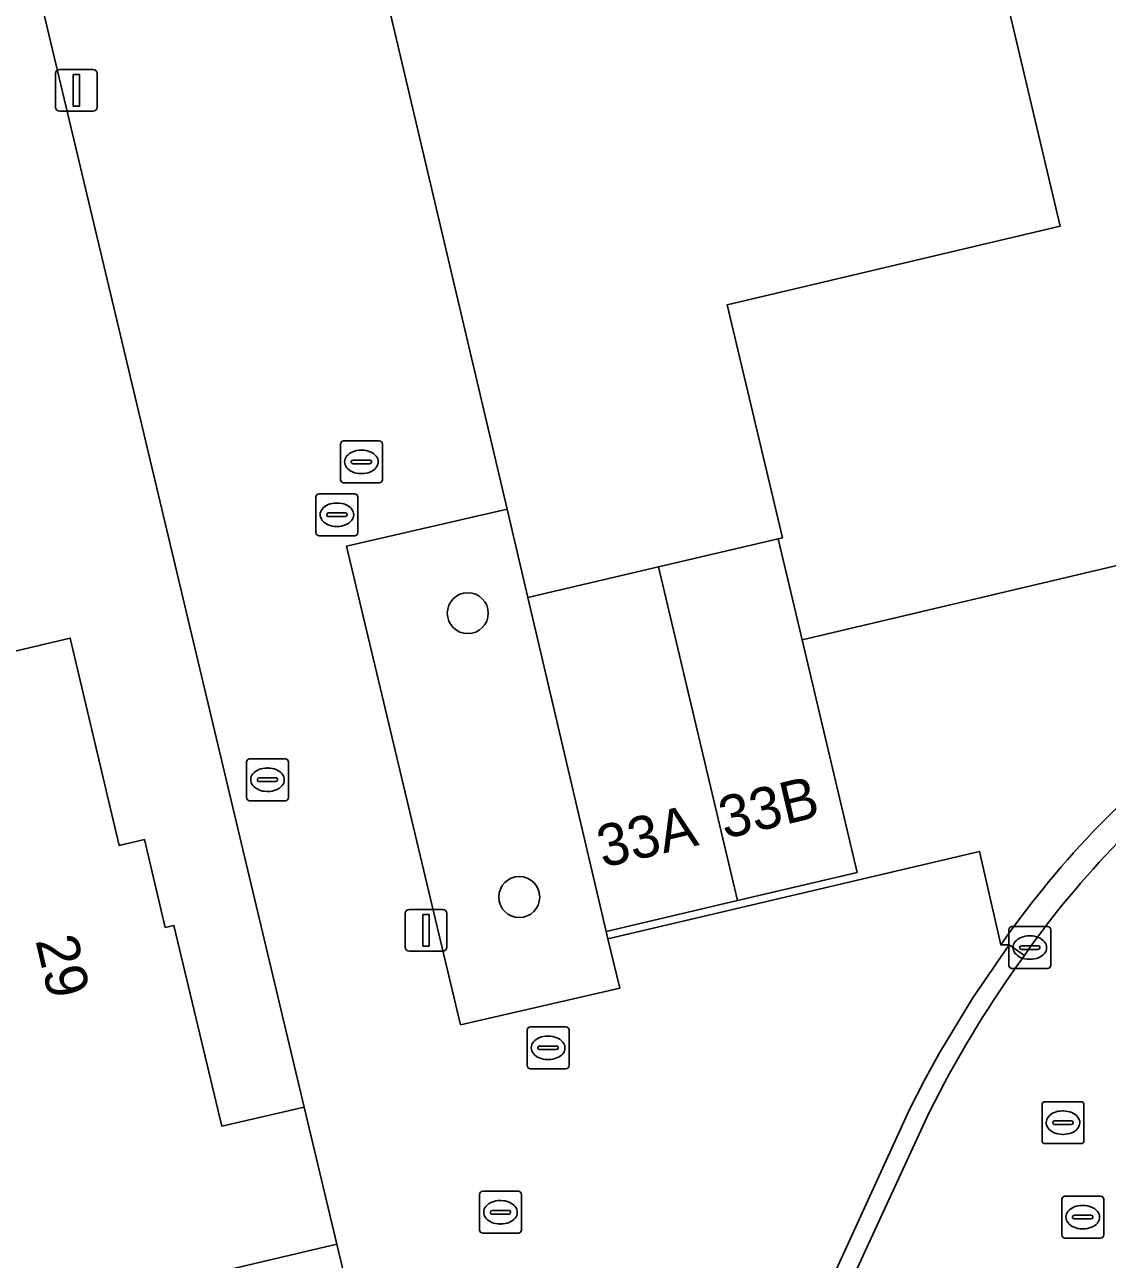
# Model space of a CAD drawing. Extents: x 157648 to 158502, y 379212 to 380938.
# Drawn here: x 158221.39 to 158247.23, y 380514.11 to 380543.57 of the extents above; entities that cross this region are included whole.
import ezdxf

# ---------------------------------------------------------------- set-up
doc = ezdxf.new("R2010")
doc.units = 0
for name, color, linetype in [('IMGEO_Boom', 7, 'Continuous'), ('IMGEO_Brandkraan', 7, 'Continuous'), ('IMGEO_Erf', 7, 'Continuous'), ('IMGEO_Groenvoorziening', 7, 'Continuous'), ('IMGEO_Hek', 7, 'Continuous'), ('IMGEO_Kolk', 7, 'Continuous'), ('IMGEO_Lichtmast', 7, 'Continuous'), ('IMGEO_Pand', 7, 'Continuous'), ('IMGEO_Pand_nummerreeks', 7, 'Continuous'), ('IMGEO_Rijbaan_lokaal_open', 7, 'Continuous'), ('IMGEO_Rioolput', 7, 'Continuous'), ('IMGEO_Voetpad_open', 7, 'Continuous')]:
    doc.layers.add(name, color=color, linetype=linetype)

msp = doc.modelspace()

# ---------------------------------------------------------------- linework, layer by layer
at = {"layer": 'IMGEO_Boom'}
for centre in [(158231.968, 380529.528), (158233.196, 380522.753)]:
    msp.add_circle(centre, 0.489, dxfattribs=at)
at = {"layer": 'IMGEO_Brandkraan'}
for p, q in [((158226.687, 380525.127), (158226.687, 380525.979)), ((158226.762, 380526.053), (158227.614, 380526.053)), ((158227.175, 380525.833), (158227.2, 380525.833)), ((158227.688, 380525.979), (158227.688, 380525.127)), ((158226.946, 380525.547), (158226.946, 380525.559)), ((158227.384, 380525.51), (158226.986, 380525.51)), ((158226.989, 380525.596), (158227.387, 380525.596)), ((158227.43, 380525.559), (158227.43, 380525.547)), ((158227.198, 380525.273), (158227.173, 380525.273)), ((158227.614, 380525.053), (158226.762, 380525.053))]:
    msp.add_line(p, q, dxfattribs=at)
for points in [[(158226.687, 380525.127), (158226.687, 380525.979)], [(158226.762, 380526.053), (158227.614, 380526.053)], [(158227.688, 380525.979), (158227.688, 380525.127)], [(158227.614, 380525.053), (158226.762, 380525.053)]]:
    msp.add_lwpolyline(points, dxfattribs=at)
for centre, radius, start, end in [((158226.764, 380525.977), 0.0765, 91.552, 178.448), ((158226.764, 380525.977), 0.0765, 91.552, 178.448), ((158227.612, 380525.977), 0.0765, 1.552, 88.448), ((158227.612, 380525.977), 0.0765, 1.552, 88.448), ((158226.986, 380525.556), 0.0403, 85.8775, 175.7526), ((158226.983, 380525.546), 0.0366, 178.938, 274.7102), ((158227.387, 380525.553), 0.043, 264.8664, 352.4533), ((158227.391, 380525.558), 0.0386, 1.7309, 96.639), ((158226.764, 380525.129), 0.0765, 181.552, 268.448), ((158226.764, 380525.129), 0.0765, 181.552, 268.448), ((158227.612, 380525.129), 0.0765, 271.552, 358.448), ((158227.612, 380525.129), 0.0765, 271.552, 358.448)]:
    msp.add_arc(centre, radius, start, end, dxfattribs=at)
for centre, major_axis, ratio, start_param, end_param in [((158227.174, 380525.553), (-0.387, 0.002), 0.722429, 4.712389, 7.853982), ((158227.199, 380525.553), (-0.39, 0.002), 0.717154, 1.570796, 4.712389)]:
    msp.add_ellipse(centre, major_axis=major_axis, ratio=ratio, start_param=start_param, end_param=end_param, dxfattribs=at)
at = {"layer": 'IMGEO_Erf'}
for points in [[(158207.911, 380501.03), (158215.154, 380502.738), (158222.749, 380504.529), (158220.849, 380512.586), (158218.887, 380512.123), (158216.994, 380520.152), (158208.234, 380518.086), (158206.561, 380525.179), (158222.48, 380528.933), (158223.648, 380523.983), (158224.253, 380524.126), (158224.748, 380522.028), (158224.955, 380522.077), (158226.095, 380517.285), (158228.061, 380517.741), (158218.496, 380557.919), (158216.938, 380564.64), (158206.036, 380574.234), (158181.237, 380547.104), (158161.46, 380525.323), (158161.459, 380525.322)], [(158226.289, 380559.958), (158230.238, 380543.354), (158232.907, 380532.013), (158233.403, 380529.904), (158236.519, 380530.635), (158239.376, 380531.305), (158239.475, 380531.328), (158238.162, 380536.889), (158246.107, 380538.764), (158244.27, 380546.547)], [(158248.401, 380530.889), (158239.946, 380528.893), (158241.258, 380523.342), (158238.401, 380522.667), (158235.273, 380521.928), (158235.314, 380521.754), (158244.18, 380523.842), (158244.692, 380521.61), (158244.875, 380521.874)]]:
    msp.add_lwpolyline(points, dxfattribs=at)
msp.add_arc((158263.238, 380508.736), 22.579, 126.1016, 144.417, dxfattribs=at)
at = {"layer": 'IMGEO_Groenvoorziening'}
msp.add_lwpolyline([(158235.314, 380521.754), (158235.273, 380521.928), (158233.403, 380529.904), (158232.907, 380532.013), (158229.076, 380531.128), (158231.797, 380519.705), (158235.594, 380520.58)], close=True, dxfattribs=at)
at = {"layer": 'IMGEO_Hek'}
for points in [[(158230.238, 380543.354), (158232.907, 380532.013)], [(158232.907, 380532.013), (158233.403, 380529.904)]]:
    msp.add_lwpolyline(points, dxfattribs=at)
at = {"layer": 'IMGEO_Kolk'}
for p, q in [((158228.344, 380531.451), (158228.344, 380532.303)), ((158228.419, 380532.377), (158229.271, 380532.377)), ((158229.345, 380532.303), (158229.345, 380531.451)), ((158228.832, 380532.157), (158228.857, 380532.157)), ((158228.603, 380531.871), (158228.603, 380531.883)), ((158229.041, 380531.834), (158228.643, 380531.834)), ((158228.646, 380531.92), (158229.044, 380531.92)), ((158229.087, 380531.883), (158229.087, 380531.871)), ((158229.271, 380531.377), (158228.419, 380531.377)), ((158228.855, 380531.597), (158228.83, 380531.597)), ((158244.88, 380521.121), (158244.88, 380521.973)), ((158244.955, 380522.047), (158245.807, 380522.047)), ((158245.881, 380521.973), (158245.881, 380521.121)), ((158245.368, 380521.827), (158245.393, 380521.827)), ((158245.139, 380521.541), (158245.139, 380521.553)), ((158245.577, 380521.504), (158245.179, 380521.504)), ((158245.182, 380521.59), (158245.58, 380521.59)), ((158245.623, 380521.553), (158245.623, 380521.541)), ((158245.391, 380521.267), (158245.366, 380521.267)), ((158245.807, 380521.047), (158244.955, 380521.047)), ((158232.248, 380514.804), (158232.248, 380515.656)), ((158232.323, 380515.73), (158233.175, 380515.73)), ((158232.736, 380515.51), (158232.761, 380515.51)), ((158233.249, 380515.656), (158233.249, 380514.804)), ((158232.507, 380515.224), (158232.507, 380515.236)), ((158232.945, 380515.187), (158232.547, 380515.187)), ((158232.55, 380515.273), (158232.948, 380515.273)), ((158232.991, 380515.236), (158232.991, 380515.224)), ((158232.759, 380514.95), (158232.734, 380514.95)), ((158233.175, 380514.73), (158232.323, 380514.73))]:
    msp.add_line(p, q, dxfattribs=at)
for points in [[(158228.344, 380531.451), (158228.344, 380532.303)], [(158228.419, 380532.377), (158229.271, 380532.377)], [(158229.345, 380532.303), (158229.345, 380531.451)], [(158229.271, 380531.377), (158228.419, 380531.377)], [(158244.88, 380521.121), (158244.88, 380521.973)], [(158244.955, 380522.047), (158245.807, 380522.047)], [(158245.881, 380521.973), (158245.881, 380521.121)], [(158245.807, 380521.047), (158244.955, 380521.047)], [(158232.248, 380514.804), (158232.248, 380515.656)], [(158232.323, 380515.73), (158233.175, 380515.73)], [(158233.249, 380515.656), (158233.249, 380514.804)], [(158233.175, 380514.73), (158232.323, 380514.73)]]:
    msp.add_lwpolyline(points, dxfattribs=at)
for centre, radius, start, end in [((158228.421, 380532.301), 0.0765, 91.552, 178.448), ((158228.421, 380532.301), 0.0765, 91.552, 178.448), ((158229.269, 380532.301), 0.0765, 1.552, 88.448), ((158229.269, 380532.301), 0.0765, 1.552, 88.448), ((158228.643, 380531.88), 0.0403, 85.8775, 175.7526), ((158228.64, 380531.87), 0.0366, 178.938, 274.7102), ((158229.044, 380531.877), 0.043, 264.8664, 352.4533), ((158229.048, 380531.882), 0.0386, 1.7309, 96.639), ((158228.421, 380531.453), 0.0765, 181.552, 268.448), ((158228.421, 380531.453), 0.0765, 181.552, 268.448), ((158229.269, 380531.453), 0.0765, 271.552, 358.448), ((158229.269, 380531.453), 0.0765, 271.552, 358.448), ((158244.957, 380521.971), 0.0765, 91.552, 178.448), ((158244.957, 380521.971), 0.0765, 91.552, 178.448), ((158245.805, 380521.971), 0.0765, 1.552, 88.448), ((158245.805, 380521.971), 0.0765, 1.552, 88.448), ((158245.179, 380521.55), 0.0403, 85.8775, 175.7526), ((158245.176, 380521.54), 0.0366, 178.938, 274.7102), ((158245.58, 380521.547), 0.043, 264.8664, 352.4533), ((158245.584, 380521.552), 0.0386, 1.7309, 96.639), ((158244.957, 380521.123), 0.0765, 181.552, 268.448), ((158244.957, 380521.123), 0.0765, 181.552, 268.448), ((158245.805, 380521.123), 0.0765, 271.552, 358.448), ((158245.805, 380521.123), 0.0765, 271.552, 358.448), ((158232.325, 380515.654), 0.0765, 91.552, 178.448), ((158232.325, 380515.654), 0.0765, 91.552, 178.448), ((158233.173, 380515.654), 0.0765, 1.552, 88.448), ((158233.173, 380515.654), 0.0765, 1.552, 88.448), ((158232.547, 380515.233), 0.0403, 85.8775, 175.7526), ((158232.544, 380515.223), 0.0366, 178.938, 274.7102), ((158232.948, 380515.23), 0.043, 264.8664, 352.4533), ((158232.952, 380515.235), 0.0386, 1.7309, 96.639), ((158232.325, 380514.806), 0.0765, 181.552, 268.448), ((158232.325, 380514.806), 0.0765, 181.552, 268.448), ((158233.173, 380514.806), 0.0765, 271.552, 358.448), ((158233.173, 380514.806), 0.0765, 271.552, 358.448)]:
    msp.add_arc(centre, radius, start, end, dxfattribs=at)
for centre, major_axis, ratio, start_param, end_param in [((158228.831, 380531.877), (-0.387, 0.002), 0.722429, 4.712389, 7.853982), ((158228.856, 380531.877), (-0.39, 0.002), 0.717154, 1.570796, 4.712389), ((158245.367, 380521.547), (-0.387, 0.002), 0.722429, 4.712389, 7.853982), ((158245.392, 380521.547), (-0.39, 0.002), 0.717154, 1.570796, 4.712389), ((158232.735, 380515.23), (-0.387, 0.002), 0.722429, 4.712389, 7.853982), ((158232.76, 380515.23), (-0.39, 0.002), 0.717154, 1.570796, 4.712389)]:
    msp.add_ellipse(centre, major_axis=major_axis, ratio=ratio, start_param=start_param, end_param=end_param, dxfattribs=at)
at = {"layer": 'IMGEO_Lichtmast'}
for p, q in [((158222.131, 380541.606), (158222.131, 380542.406)), ((158222.131, 380542.406), (158222.131, 380541.606)), ((158222.231, 380542.506), (158223.021, 380542.506)), ((158223.021, 380542.506), (158222.231, 380542.506)), ((158223.121, 380542.406), (158223.121, 380541.606)), ((158223.121, 380541.606), (158223.121, 380542.406)), ((158223.021, 380541.506), (158222.231, 380541.506)), ((158222.231, 380541.506), (158223.021, 380541.506)), ((158230.476, 380521.558), (158230.476, 380522.358)), ((158230.476, 380522.358), (158230.476, 380521.558)), ((158230.576, 380522.458), (158231.366, 380522.458)), ((158231.366, 380522.458), (158230.576, 380522.458)), ((158231.466, 380522.358), (158231.466, 380521.558)), ((158231.466, 380521.558), (158231.466, 380522.358)), ((158231.366, 380521.458), (158230.576, 380521.458)), ((158230.576, 380521.458), (158231.366, 380521.458))]:
    msp.add_line(p, q, dxfattribs=at)
for points in [[(158222.551, 380542.381), (158222.701, 380542.381), (158222.701, 380541.631), (158222.551, 380541.631), (158222.551, 380542.381)], [(158230.896, 380522.333), (158231.046, 380522.333), (158231.046, 380521.583), (158230.896, 380521.583), (158230.896, 380522.333)]]:
    msp.add_lwpolyline(points, dxfattribs=at)
for centre, start, end in [((158222.231, 380542.406), 90, 180), ((158222.231, 380542.406), 90, 180), ((158223.021, 380542.406), 0, 90), ((158223.021, 380542.406), 360, 90), ((158222.231, 380541.606), 180, 270), ((158222.231, 380541.606), 180, 270), ((158223.021, 380541.606), 270, 0), ((158223.021, 380541.606), 270, 0), ((158230.576, 380522.358), 90, 180), ((158230.576, 380522.358), 90, 180), ((158231.366, 380522.358), 0, 90), ((158231.366, 380522.358), 360, 90), ((158230.576, 380521.558), 180, 270), ((158230.576, 380521.558), 180, 270), ((158231.366, 380521.558), 270, 0), ((158231.366, 380521.558), 270, 0)]:
    msp.add_arc(centre, 0.1, start, end, dxfattribs=at)
at = {"layer": 'IMGEO_Pand'}
for points in [[(158254.07, 380537.657), (158252.147, 380545.356), (158252.047, 380545.332), (158251.36, 380548.241), (158247.079, 380547.23), (158244.27, 380546.547), (158246.107, 380538.764), (158238.162, 380536.889), (158239.475, 380531.328), (158239.376, 380531.305), (158239.946, 380528.893), (158248.401, 380530.889), (158248.359, 380531.07), (158250.471, 380531.569), (158250.256, 380532.48), (158255.026, 380533.607)], [(158239.946, 380528.893), (158239.376, 380531.305), (158236.519, 380530.635), (158238.401, 380522.667), (158241.258, 380523.342)], [(158236.519, 380530.635), (158233.403, 380529.904), (158235.273, 380521.928), (158238.401, 380522.667)], [(158220.849, 380512.586), (158228.842, 380514.468), (158228.061, 380517.741), (158226.095, 380517.285), (158224.955, 380522.077), (158224.748, 380522.028), (158224.253, 380524.126), (158223.648, 380523.983), (158222.48, 380528.933), (158206.561, 380525.179), (158208.234, 380518.086), (158216.994, 380520.152), (158218.887, 380512.123)], [(158216.91, 380495.301), (158231.694, 380498.797), (158231.45, 380500), (158230.488, 380504.077), (158231.09, 380504.219), (158230.682, 380505.946), (158230.849, 380505.985), (158229.701, 380510.871), (158228.842, 380514.468), (158220.849, 380512.586), (158222.749, 380504.529), (158215.154, 380502.738), (158215.8, 380500)]]:
    msp.add_lwpolyline(points, close=True, dxfattribs=at)
at = {"layer": 'IMGEO_Rijbaan_lokaal_open'}
for points in [[(158245.381, 380521.547), (158245.253, 380521.357)], [(158243.108, 380517.861), (158243.014, 380517.675), (158242.921, 380517.489), (158240.071, 380511.301), (158235.142, 380500.539)]]:
    msp.add_lwpolyline(points, dxfattribs=at)
for centre, radius, start, end in [((158263.464, 380508.509), 22.294, 126.211, 144.2073), ((158266.453, 380505.943), 26.211, 143.981, 152.9559)]:
    msp.add_arc(centre, radius, start, end, dxfattribs=at)
at = {"layer": 'IMGEO_Rioolput'}
for p, q in [((158228.928, 380532.712), (158228.928, 380533.564)), ((158229.003, 380533.638), (158229.855, 380533.638)), ((158229.929, 380533.564), (158229.929, 380532.712)), ((158229.187, 380533.132), (158229.187, 380533.144)), ((158229.23, 380533.181), (158229.628, 380533.181)), ((158229.416, 380533.418), (158229.441, 380533.418)), ((158229.671, 380533.144), (158229.671, 380533.132)), ((158229.625, 380533.095), (158229.227, 380533.095)), ((158229.439, 380532.858), (158229.414, 380532.858)), ((158229.855, 380532.638), (158229.003, 380532.638)), ((158233.384, 380518.729), (158233.384, 380519.581)), ((158233.459, 380519.655), (158234.311, 380519.655)), ((158234.385, 380519.581), (158234.385, 380518.729)), ((158233.872, 380519.435), (158233.897, 380519.435)), ((158233.643, 380519.149), (158233.643, 380519.161)), ((158234.081, 380519.112), (158233.683, 380519.112)), ((158233.686, 380519.198), (158234.084, 380519.198)), ((158234.127, 380519.161), (158234.127, 380519.149)), ((158233.895, 380518.875), (158233.87, 380518.875)), ((158234.311, 380518.655), (158233.459, 380518.655)), ((158245.747, 380517.869), (158246.599, 380517.869)), ((158245.672, 380516.943), (158245.672, 380517.795)), ((158246.16, 380517.649), (158246.185, 380517.649)), ((158246.673, 380517.795), (158246.673, 380516.943)), ((158245.931, 380517.363), (158245.931, 380517.375)), ((158246.369, 380517.326), (158245.971, 380517.326)), ((158245.974, 380517.412), (158246.372, 380517.412)), ((158246.415, 380517.375), (158246.415, 380517.363)), ((158246.183, 380517.089), (158246.158, 380517.089)), ((158246.599, 380516.869), (158245.747, 380516.869)), ((158246.144, 380514.688), (158246.144, 380515.54)), ((158246.219, 380515.614), (158247.071, 380515.614)), ((158247.145, 380515.54), (158247.145, 380514.688)), ((158246.632, 380515.394), (158246.657, 380515.394)), ((158246.403, 380515.108), (158246.403, 380515.12)), ((158246.841, 380515.071), (158246.443, 380515.071)), ((158246.446, 380515.157), (158246.844, 380515.157)), ((158246.887, 380515.12), (158246.887, 380515.108)), ((158247.071, 380514.614), (158246.219, 380514.614)), ((158246.655, 380514.834), (158246.63, 380514.834))]:
    msp.add_line(p, q, dxfattribs=at)
for points in [[(158228.928, 380532.712), (158228.928, 380533.564)], [(158229.003, 380533.638), (158229.855, 380533.638)], [(158229.929, 380533.564), (158229.929, 380532.712)], [(158229.855, 380532.638), (158229.003, 380532.638)], [(158233.384, 380518.729), (158233.384, 380519.581)], [(158233.459, 380519.655), (158234.311, 380519.655)], [(158234.385, 380519.581), (158234.385, 380518.729)], [(158234.311, 380518.655), (158233.459, 380518.655)], [(158245.747, 380517.869), (158246.599, 380517.869)], [(158245.672, 380516.943), (158245.672, 380517.795)], [(158246.673, 380517.795), (158246.673, 380516.943)], [(158246.599, 380516.869), (158245.747, 380516.869)], [(158246.144, 380514.688), (158246.144, 380515.54)], [(158246.219, 380515.614), (158247.071, 380515.614)], [(158247.145, 380515.54), (158247.145, 380514.688)], [(158247.071, 380514.614), (158246.219, 380514.614)]]:
    msp.add_lwpolyline(points, dxfattribs=at)
for centre, radius, start, end in [((158229.005, 380533.562), 0.0765, 91.552, 178.448), ((158229.005, 380533.562), 0.0765, 91.552, 178.448), ((158229.853, 380533.562), 0.0765, 1.552, 88.448), ((158229.853, 380533.562), 0.0765, 1.552, 88.448), ((158229.227, 380533.141), 0.0403, 85.8775, 175.7526), ((158229.632, 380533.143), 0.0386, 1.7309, 96.639), ((158229.224, 380533.131), 0.0366, 178.938, 274.7102), ((158229.628, 380533.138), 0.043, 264.8664, 352.4533), ((158229.005, 380532.714), 0.0765, 181.552, 268.448), ((158229.005, 380532.714), 0.0765, 181.552, 268.448), ((158229.853, 380532.714), 0.0765, 271.552, 358.448), ((158229.853, 380532.714), 0.0765, 271.552, 358.448), ((158233.461, 380519.579), 0.0765, 91.552, 178.448), ((158233.461, 380519.579), 0.0765, 91.552, 178.448), ((158234.309, 380519.579), 0.0765, 1.552, 88.448), ((158234.309, 380519.579), 0.0765, 1.552, 88.448), ((158233.683, 380519.158), 0.0403, 85.8775, 175.7526), ((158233.68, 380519.148), 0.0366, 178.938, 274.7102), ((158234.084, 380519.155), 0.043, 264.8664, 352.4533), ((158234.088, 380519.16), 0.0386, 1.7309, 96.639), ((158233.461, 380518.731), 0.0765, 181.552, 268.448), ((158233.461, 380518.731), 0.0765, 181.552, 268.448), ((158234.309, 380518.731), 0.0765, 271.552, 358.448), ((158234.309, 380518.731), 0.0765, 271.552, 358.448), ((158245.749, 380517.793), 0.0765, 91.552, 178.448), ((158245.749, 380517.793), 0.0765, 91.552, 178.448), ((158246.597, 380517.793), 0.0765, 1.552, 88.448), ((158246.597, 380517.793), 0.0765, 1.552, 88.448), ((158245.971, 380517.372), 0.0403, 85.8775, 175.7526), ((158245.968, 380517.362), 0.0366, 178.938, 274.7102), ((158246.372, 380517.369), 0.043, 264.8664, 352.4533), ((158246.376, 380517.374), 0.0386, 1.7309, 96.639), ((158245.749, 380516.945), 0.0765, 181.552, 268.448), ((158245.749, 380516.945), 0.0765, 181.552, 268.448), ((158246.597, 380516.945), 0.0765, 271.552, 358.448), ((158246.597, 380516.945), 0.0765, 271.552, 358.448), ((158246.221, 380515.538), 0.0765, 91.552, 178.448), ((158246.221, 380515.538), 0.0765, 91.552, 178.448), ((158247.069, 380515.538), 0.0765, 1.552, 88.448), ((158247.069, 380515.538), 0.0765, 1.552, 88.448), ((158246.443, 380515.117), 0.0403, 85.8775, 175.7526), ((158246.44, 380515.107), 0.0366, 178.938, 274.7102), ((158246.844, 380515.114), 0.043, 264.8664, 352.4533), ((158246.848, 380515.119), 0.0386, 1.7309, 96.639), ((158246.221, 380514.69), 0.0765, 181.552, 268.448), ((158246.221, 380514.69), 0.0765, 181.552, 268.448), ((158247.069, 380514.69), 0.0765, 271.552, 358.448), ((158247.069, 380514.69), 0.0765, 271.552, 358.448)]:
    msp.add_arc(centre, radius, start, end, dxfattribs=at)
for centre, major_axis, ratio, start_param, end_param in [((158229.415, 380533.138), (-0.387, 0.002), 0.722429, 4.712389, 7.853982), ((158229.44, 380533.138), (-0.39, 0.002), 0.717154, 1.570796, 4.712389), ((158233.871, 380519.155), (-0.387, 0.002), 0.722429, 4.712389, 7.853982), ((158233.896, 380519.155), (-0.39, 0.002), 0.717154, 1.570796, 4.712389), ((158246.159, 380517.369), (-0.387, 0.002), 0.722429, 4.712389, 7.853982), ((158246.184, 380517.369), (-0.39, 0.002), 0.717154, 1.570796, 4.712389), ((158246.631, 380515.114), (-0.387, 0.002), 0.722429, 4.712389, 7.853982), ((158246.656, 380515.114), (-0.39, 0.002), 0.717154, 1.570796, 4.712389)]:
    msp.add_ellipse(centre, major_axis=major_axis, ratio=ratio, start_param=start_param, end_param=end_param, dxfattribs=at)
at = {"layer": 'IMGEO_Voetpad_open'}
for points in [[(158230.238, 380543.354), (158226.289, 380559.958), (158225.417, 380563.757), (158223.255, 380573.155), (158220.689, 380572.538), (158218.078, 380583.925), (158217.925, 380584.488)], [(158209.549, 380578.944), (158208.577, 380577.884), (158208.994, 380577.47), (158219.876, 380569.535), (158222.404, 380558.759), (158218.496, 380557.919), (158228.061, 380517.741), (158228.842, 380514.468), (158229.701, 380510.871)], [(158239.674, 380511.491), (158242.512, 380517.683), (158242.859, 380518.366), (158243.226, 380519.039), (158244.019, 380520.35), (158244.887, 380521.613), (158244.692, 380521.61), (158244.18, 380523.842), (158235.314, 380521.754), (158235.594, 380520.58), (158231.797, 380519.705), (158229.076, 380531.128), (158232.907, 380532.013), (158230.238, 380543.354)], [(158244.875, 380521.874), (158244.692, 380521.61), (158244.887, 380521.613), (158245.253, 380521.357), (158245.381, 380521.547)], [(158245.253, 380521.357), (158244.887, 380521.613), (158244.019, 380520.35), (158243.226, 380519.039), (158242.859, 380518.366), (158242.512, 380517.683), (158239.674, 380511.491), (158239.414, 380511.303), (158234.589, 380500.786)], [(158240.071, 380511.301), (158242.921, 380517.489), (158243.014, 380517.675), (158243.108, 380517.861)]]:
    msp.add_lwpolyline(points, dxfattribs=at)
for centre, radius, start, end in [((158263.238, 380508.736), 22.579, 126.1016, 144.417), ((158263.464, 380508.509), 22.294, 126.211, 144.2073), ((158266.453, 380505.943), 26.211, 143.981, 152.9559)]:
    msp.add_arc(centre, radius, start, end, dxfattribs=at)

# ---------------------------------------------------------------- texts
at = {"layer": 'IMGEO_Pand_nummerreeks'}
for s, rotation, p in [('33B', 13.2926, (158238.1, 380524.137)), ('33A', 13.2926, (158235.192, 380523.45)), ('29', 283.2738, (158221.647, 380521.72))]:
    msp.add_text(s, height=1, rotation=rotation, dxfattribs=at).set_placement(p)

doc.saveas('drawing.dxf')
